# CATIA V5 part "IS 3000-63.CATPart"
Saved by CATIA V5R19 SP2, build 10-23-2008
Part number: IS 3000-63
Bounding box of the stored display mesh (mm): x -47.487 to 47.487, y -47.487 to 47.487, z 0 to 247
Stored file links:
  C:\Users\Bora\Desktop\3D Katı model\IS serisi\IS 3000\IS 3000-63.CATPart
  C:\Program Files\Dassault Systemes\B19\intel_a\reffiles\standard\MetricThickPitch.txt
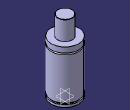
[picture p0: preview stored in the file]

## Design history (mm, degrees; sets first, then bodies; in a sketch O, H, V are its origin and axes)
Body1 (main body)
  Sketch1 on yz-plane, origin (0, 0, 0), H (0, 1, 0), V (0, 0, 1)
    point P1 (47.5, 162.5)
    point P4 (47.5, 157.5)
    point P7 (25, 246)
    point P9 (25, 246)
    point P13 (47.5, 162.5)
    point P14 (47.5, 157.5)
    line L1 (47.5, 162.5) -> (47.5, 181)
    line L2 (47.5, 13) -> (47.5, 157.5)
    line L3 (43.5, 13) -> (43.5, 8)
    arc A1 centre (24, 246) radius 1 from (25, 246) to (24, 247) ccw
    line L4 (25, 246) -> (25, 181)
    line L5 (47.5, 0) -> (47.5, 8)
    arc A2 centre (47.5, 160) radius 2.5 from (47.5, 162.5) to (47.5, 157.5) ccw
    line L6 (24, 247) -> (0, 247)
    point P15 (0, 247)
    line L7 (25, 181) -> (47.5, 181)
    line L8 (0, 0) -> (47.5, 0)
    line L9 (43.5, 8) -> (47.5, 8)
    line L10 (43.5, 13) -> (47.5, 13)
    coincidence: P15 V, P1 P13, P4 P14, P7 P9
    tangency: L6 A1
    horizontal: L7 H, L8 H, L9 H, L10 H
  Shaft1: profile Sketch1, axis Sketch1.V, angle 360
  Sketch2 on face of Shaft1 from Sketch1.L8, origin (0, 0, 0), H (1, 0, 0), V (0, -1, 0)
    point P1 (30, 0)
    distance P1 V = 30
  Hole1: placed by Sketch2, at (30, 0, 0) direction (0, 0, 1), diameter 6.647, depth 13, threaded "M8", thread diameter 8, thread depth 13, pitch 1.25
  CircPattern1: of Hole1, instances 4, angular step 90, axis from xy-plane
